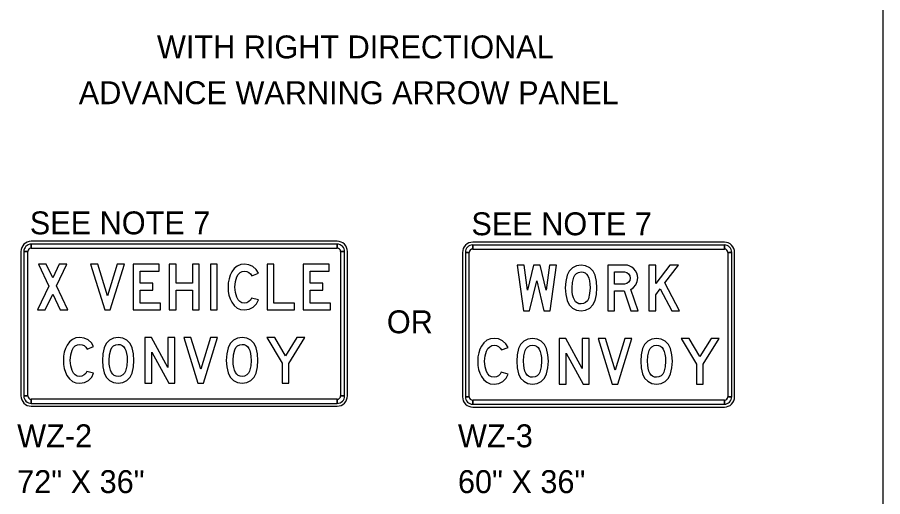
# Model space of a CAD drawing. Extents: x 1416408 to 1429341, y 372694 to 383211.
# Drawn here: x 1427719.8 to 1428099.1, y 373820.1 to 374030.4 of the extents above; entities that cross this region are included whole.
import ezdxf

# ---------------------------------------------------------------- set-up
doc = ezdxf.new("R2010")
doc.units = 0
doc.layers.add('Working Level 1', color=7, linetype='Continuous')

msp = doc.modelspace()

# ---------------------------------------------------------------- linework, layer by layer
at = {"layer": 'Working Level 1'}
for p, q in [((1428099.08, 374447.3), (1428099.08, 372727.17)), ((1427859.99, 373932.16), (1427725.85, 373932.16)), ((1428029.69, 373931.77), (1427919.39, 373931.77)), ((1427721.37, 373927.64), (1427721.37, 373864.35)), ((1427722.62, 373927.64), (1427724.35, 373927.64)), ((1427725.85, 373929.15), (1427725.85, 373930.9)), ((1427859.99, 373930.9), (1427859.99, 373929.15)), ((1427861.48, 373927.64), (1427863.22, 373927.64)), ((1427864.46, 373864.35), (1427864.46, 373927.64)), ((1427919.39, 373928.75), (1427919.39, 373930.51)), ((1428029.69, 373930.51), (1428029.69, 373928.75)), ((1427914.92, 373927.25), (1427914.92, 373863.96)), ((1427916.17, 373927.25), (1427917.9, 373927.25)), ((1428031.18, 373927.25), (1428032.92, 373927.25)), ((1428034.16, 373863.96), (1428034.16, 373927.25)), ((1427724.35, 373864.35), (1427722.62, 373864.35)), ((1427725.85, 373861.08), (1427725.85, 373862.84)), ((1427859.99, 373862.84), (1427859.99, 373861.08)), ((1427863.22, 373864.35), (1427861.48, 373864.35)), ((1427917.9, 373863.96), (1427916.17, 373863.96)), ((1428032.92, 373863.96), (1428031.18, 373863.96)), ((1427725.85, 373859.83), (1427859.99, 373859.83)), ((1427919.39, 373860.69), (1427919.39, 373862.45)), ((1427919.39, 373859.44), (1428029.69, 373859.44)), ((1428029.69, 373862.45), (1428029.69, 373860.69))]:
    msp.add_line(p, q, dxfattribs=at)
for points in [[(1427722.62, 373927.64), (1427722.62, 373864.35), (1427724.35, 373864.35), (1427724.35, 373927.64), (1427722.62, 373927.64)], [(1427859.99, 373930.9), (1427725.85, 373930.9), (1427725.85, 373929.15), (1427859.99, 373929.15), (1427859.99, 373930.9)], [(1427863.22, 373864.35), (1427863.22, 373927.64), (1427861.48, 373927.64), (1427861.48, 373864.35), (1427863.22, 373864.35)], [(1428029.69, 373930.51), (1427919.39, 373930.51), (1427919.39, 373928.75), (1428029.69, 373928.75), (1428029.69, 373930.51)], [(1427916.17, 373927.25), (1427916.17, 373863.96), (1427917.9, 373863.96), (1427917.9, 373927.25), (1427916.17, 373927.25)], [(1428032.92, 373863.96), (1428032.92, 373927.25), (1428031.18, 373927.25), (1428031.18, 373863.96), (1428032.92, 373863.96)], [(1427741.9, 373902.02), (1427736.95, 373912.54), (1427741.49, 373922.11), (1427738.17, 373922.11), (1427735.29, 373916.05), (1427732.43, 373922.11), (1427729.1, 373922.11), (1427733.62, 373912.52), (1427728.64, 373902.02), (1427731.96, 373902.02), (1427735.28, 373909), (1427738.58, 373902.02)], [(1427766.73, 373922.11), (1427763.59, 373922.11), (1427759.32, 373908.23), (1427755.06, 373922.11), (1427751.93, 373922.11), (1427758.08, 373902.02), (1427760.55, 373902.02)], [(1427782.57, 373905.05), (1427773.56, 373905.05), (1427773.56, 373910.74), (1427779.18, 373910.74), (1427779.18, 373913.77), (1427773.56, 373913.77), (1427773.56, 373919.08), (1427781.96, 373919.08), (1427781.96, 373922.11), (1427770.56, 373922.11), (1427770.56, 373902.02), (1427782.57, 373902.02)], [(1427799.52, 373902.02), (1427799.52, 373922.11), (1427796.52, 373922.11), (1427796.52, 373913.77), (1427789.39, 373913.77), (1427789.39, 373922.11), (1427786.39, 373922.11), (1427786.39, 373902.02), (1427789.39, 373902.02), (1427789.39, 373910.74), (1427796.52, 373910.74), (1427796.52, 373902.02)], [(1427807.4, 373902.02), (1427807.4, 373922.11), (1427804.41, 373922.11), (1427804.41, 373902.02)], [(1427825.43, 373906.48), (1427822.43, 373907.25), (1427821.98, 373906.37), (1427821.26, 373905.67), (1427820.32, 373905.21), (1427819.29, 373905.05), (1427818.24, 373905.21), (1427817.35, 373905.69), (1427816.59, 373906.49), (1427815.98, 373907.61), (1427815.37, 373909.67), (1427815.17, 373912.07), (1427815.37, 373914.47), (1427816.01, 373916.54), (1427816.63, 373917.65), (1427817.41, 373918.44), (1427818.32, 373918.92), (1427819.39, 373919.08), (1427820.38, 373918.94), (1427821.28, 373918.52), (1427822.04, 373917.87), (1427822.55, 373917.02), (1427825.43, 373918.17), (1427824.46, 373919.78), (1427823.04, 373921.03), (1427821.32, 373921.84), (1427819.43, 373922.11), (1427817.68, 373921.9), (1427816.16, 373921.27), (1427814.85, 373920.22), (1427813.77, 373918.76), (1427813.07, 373917.31), (1427812.57, 373915.72), (1427812.27, 373913.97), (1427812.17, 373912.08), (1427812.26, 373910.19), (1427812.56, 373908.45), (1427813.05, 373906.85), (1427813.75, 373905.41), (1427814.81, 373903.92), (1427816.1, 373902.87), (1427817.61, 373902.23), (1427819.33, 373902.02), (1427821.35, 373902.33), (1427823.17, 373903.26), (1427824.59, 373904.69)], [(1427841.26, 373902.02), (1427841.26, 373905.05), (1427832.25, 373905.05), (1427832.25, 373922.11), (1427829.25, 373922.11), (1427829.25, 373902.02)], [(1427857.1, 373905.05), (1427848.08, 373905.05), (1427848.08, 373910.74), (1427853.71, 373910.74), (1427853.71, 373913.77), (1427848.08, 373913.77), (1427848.08, 373919.08), (1427856.49, 373919.08), (1427856.49, 373922.11), (1427845.09, 373922.11), (1427845.09, 373902.02), (1427857.1, 373902.02)], [(1427956.1, 373921.72), (1427953.07, 373921.72), (1427951.54, 373910.71), (1427948.91, 373921.72), (1427946.01, 373921.72), (1427943.39, 373910.7), (1427941.87, 373921.72), (1427938.83, 373921.72), (1427941.62, 373901.63), (1427944.32, 373901.63), (1427947.47, 373914.85), (1427950.61, 373901.63), (1427953.32, 373901.63)], [(1427973.82, 373911.69), (1427973.62, 373914.55), (1427973.01, 373917.24), (1427972.12, 373919.05), (1427970.69, 373920.48), (1427968.89, 373921.41), (1427966.87, 373921.72), (1427964.85, 373921.41), (1427963.06, 373920.48), (1427961.65, 373919.04), (1427960.76, 373917.22), (1427960.15, 373914.54), (1427959.95, 373911.69), (1427960.15, 373908.84), (1427960.76, 373906.15), (1427961.65, 373904.32), (1427963.06, 373902.88), (1427964.85, 373901.94), (1427966.87, 373901.63), (1427968.89, 373901.94), (1427970.68, 373902.87), (1427972.1, 373904.29), (1427972.99, 373906.11), (1427973.61, 373908.81)], [(1427991.84, 373901.63), (1427988.7, 373911.01), (1427989.93, 373911.88), (1427990.88, 373913.09), (1427991.5, 373914.52), (1427991.7, 373916.08), (1427991.6, 373917.19), (1427991.29, 373918.23), (1427990.77, 373919.19), (1427990.05, 373920.06), (1427989.18, 373920.79), (1427988.23, 373921.31), (1427987.19, 373921.61), (1427986.08, 373921.72), (1427978.58, 373921.72), (1427978.58, 373901.63), (1427981.58, 373901.63), (1427981.58, 373910.35), (1427985.74, 373910.35), (1427988.68, 373901.63)], [(1428010.05, 373901.63), (1428003.6, 373913.87), (1428009.57, 373921.72), (1428005.79, 373921.72), (1427999.59, 373913.58), (1427999.59, 373921.72), (1427996.59, 373921.72), (1427996.59, 373901.63), (1427999.59, 373901.63), (1427999.59, 373908.61), (1428001.59, 373911.23), (1428006.65, 373901.63)], [(1427970.82, 373911.67), (1427970.64, 373909.23), (1427970.12, 373906.96), (1427969.64, 373906.02), (1427968.89, 373905.28), (1427967.96, 373904.82), (1427966.9, 373904.66), (1427965.96, 373904.77), (1427965.16, 373905.1), (1427964.48, 373905.65), (1427963.93, 373906.42), (1427963.5, 373907.4), (1427963.19, 373908.61), (1427963, 373910.03), (1427962.95, 373911.67), (1427963.12, 373914.1), (1427963.65, 373916.37), (1427964.12, 373917.32), (1427964.87, 373918.06), (1427965.81, 373918.53), (1427966.9, 373918.69), (1427967.81, 373918.58), (1427968.61, 373918.25), (1427969.28, 373917.7), (1427969.84, 373916.93), (1427970.26, 373915.95), (1427970.57, 373914.74), (1427970.76, 373913.31)], [(1427981.58, 373913.38), (1427981.58, 373918.69), (1427985.95, 373918.69), (1427986.9, 373918.49), (1427987.71, 373917.9), (1427988.26, 373917.04), (1427988.44, 373916.03), (1427988.26, 373915.01), (1427987.71, 373914.16), (1427986.9, 373913.57), (1427985.95, 373913.38)], [(1427753.24, 373874.33), (1427750.23, 373875.1), (1427749.79, 373874.22), (1427749.06, 373873.52), (1427748.13, 373873.06), (1427747.09, 373872.91), (1427746.05, 373873.06), (1427745.15, 373873.55), (1427744.4, 373874.35), (1427743.79, 373875.46), (1427743.17, 373877.53), (1427742.97, 373879.92), (1427743.18, 373882.32), (1427743.81, 373884.39), (1427744.44, 373885.5), (1427745.21, 373886.29), (1427746.12, 373886.77), (1427747.19, 373886.93), (1427748.18, 373886.79), (1427749.09, 373886.38), (1427749.84, 373885.72), (1427750.35, 373884.88), (1427753.24, 373886.02), (1427752.26, 373887.63), (1427750.85, 373888.89), (1427749.12, 373889.69), (1427747.24, 373889.96), (1427745.48, 373889.75), (1427743.96, 373889.13), (1427742.66, 373888.08), (1427741.57, 373886.61), (1427740.87, 373885.16), (1427740.37, 373883.57), (1427740.07, 373881.82), (1427739.97, 373879.93), (1427740.07, 373878.04), (1427740.36, 373876.3), (1427740.86, 373874.71), (1427741.55, 373873.26), (1427742.61, 373871.77), (1427743.9, 373870.72), (1427745.41, 373870.08), (1427747.14, 373869.87), (1427749.16, 373870.18), (1427750.97, 373871.11), (1427752.39, 373872.54)], [(1427770.92, 373879.93), (1427770.72, 373882.8), (1427770.12, 373885.48), (1427769.22, 373887.29), (1427767.8, 373888.73), (1427766, 373889.65), (1427763.98, 373889.96), (1427761.95, 373889.65), (1427760.17, 373888.73), (1427758.75, 373887.29), (1427757.86, 373885.46), (1427757.25, 373882.78), (1427757.05, 373879.93), (1427757.25, 373877.08), (1427757.86, 373874.39), (1427758.75, 373872.57), (1427760.17, 373871.13), (1427761.95, 373870.19), (1427763.98, 373869.87), (1427765.99, 373870.18), (1427767.78, 373871.11), (1427769.2, 373872.54), (1427770.1, 373874.36), (1427770.71, 373877.05)], [(1427788.81, 373869.87), (1427788.81, 373889.96), (1427785.81, 373889.96), (1427785.81, 373876.76), (1427778.57, 373889.96), (1427775.68, 373889.96), (1427775.68, 373869.87), (1427778.68, 373869.87), (1427778.68, 373883.5), (1427786.16, 373869.87)], [(1427807.56, 373889.96), (1427804.42, 373889.96), (1427800.15, 373876.08), (1427795.9, 373889.96), (1427792.76, 373889.96), (1427798.92, 373869.87), (1427801.39, 373869.87)], [(1427825.26, 373879.93), (1427825.06, 373882.8), (1427824.46, 373885.48), (1427823.56, 373887.29), (1427822.14, 373888.73), (1427820.34, 373889.65), (1427818.32, 373889.96), (1427816.3, 373889.65), (1427814.51, 373888.73), (1427813.09, 373887.29), (1427812.2, 373885.46), (1427811.59, 373882.78), (1427811.39, 373879.93), (1427811.59, 373877.08), (1427812.2, 373874.39), (1427813.09, 373872.57), (1427814.51, 373871.13), (1427816.3, 373870.19), (1427818.32, 373869.87), (1427820.33, 373870.18), (1427822.13, 373871.11), (1427823.54, 373872.54), (1427824.44, 373874.36), (1427825.05, 373877.05)], [(1427845.75, 373889.96), (1427842.23, 373889.96), (1427837.35, 373881.94), (1427832.58, 373889.96), (1427829.09, 373889.96), (1427835.84, 373878.67), (1427835.84, 373869.87), (1427838.84, 373869.87), (1427838.84, 373878.59)], [(1427934.86, 373873.94), (1427931.86, 373874.71), (1427931.41, 373873.83), (1427930.68, 373873.13), (1427929.75, 373872.67), (1427928.72, 373872.51), (1427927.67, 373872.67), (1427926.78, 373873.15), (1427926.02, 373873.95), (1427925.41, 373875.07), (1427924.8, 373877.13), (1427924.6, 373879.53), (1427924.8, 373881.93), (1427925.43, 373884), (1427926.06, 373885.11), (1427926.84, 373885.9), (1427927.75, 373886.38), (1427928.82, 373886.54), (1427929.81, 373886.4), (1427930.71, 373885.98), (1427931.46, 373885.33), (1427931.98, 373884.49), (1427934.86, 373885.63), (1427933.89, 373887.24), (1427932.47, 373888.5), (1427930.75, 373889.3), (1427928.86, 373889.57), (1427927.11, 373889.36), (1427925.59, 373888.73), (1427924.28, 373887.68), (1427923.2, 373886.22), (1427922.49, 373884.77), (1427922, 373883.18), (1427921.7, 373881.43), (1427921.6, 373879.54), (1427921.69, 373877.65), (1427921.99, 373875.91), (1427922.48, 373874.31), (1427923.18, 373872.87), (1427924.24, 373871.38), (1427925.53, 373870.33), (1427927.04, 373869.69), (1427928.76, 373869.48), (1427930.78, 373869.79), (1427932.6, 373870.72), (1427934.02, 373872.15)], [(1427952.55, 373879.54), (1427952.35, 373882.41), (1427951.74, 373885.09), (1427950.85, 373886.9), (1427949.42, 373888.34), (1427947.62, 373889.26), (1427945.6, 373889.57), (1427943.58, 373889.26), (1427941.79, 373888.34), (1427940.38, 373886.9), (1427939.49, 373885.07), (1427938.88, 373882.39), (1427938.68, 373879.54), (1427938.88, 373876.69), (1427939.49, 373874), (1427940.38, 373872.18), (1427941.79, 373870.74), (1427943.58, 373869.79), (1427945.6, 373869.48), (1427947.62, 373869.79), (1427949.41, 373870.72), (1427950.83, 373872.15), (1427951.72, 373873.97), (1427952.34, 373876.66)], [(1427970.43, 373869.48), (1427970.43, 373889.57), (1427967.43, 373889.57), (1427967.43, 373876.36), (1427960.19, 373889.57), (1427957.31, 373889.57), (1427957.31, 373869.48), (1427960.31, 373869.48), (1427960.31, 373883.11), (1427967.78, 373869.48)], [(1427989.19, 373889.57), (1427986.05, 373889.57), (1427981.78, 373875.69), (1427977.52, 373889.57), (1427974.39, 373889.57), (1427980.54, 373869.48), (1427983.01, 373869.48)], [(1428006.89, 373879.54), (1428006.69, 373882.41), (1428006.08, 373885.09), (1428005.19, 373886.9), (1428003.76, 373888.34), (1428001.96, 373889.26), (1427999.94, 373889.57), (1427997.92, 373889.26), (1427996.13, 373888.34), (1427994.72, 373886.9), (1427993.83, 373885.07), (1427993.22, 373882.39), (1427993.02, 373879.54), (1427993.22, 373876.69), (1427993.83, 373874), (1427994.72, 373872.18), (1427996.13, 373870.74), (1427997.92, 373869.79), (1427999.94, 373869.48), (1428001.96, 373869.79), (1428003.75, 373870.72), (1428005.17, 373872.15), (1428006.07, 373873.97), (1428006.68, 373876.66)], [(1428027.37, 373889.57), (1428023.85, 373889.57), (1428018.98, 373881.55), (1428014.21, 373889.57), (1428010.72, 373889.57), (1428017.47, 373878.28), (1428017.47, 373869.48), (1428020.46, 373869.48), (1428020.46, 373878.2)], [(1427767.92, 373879.92), (1427767.75, 373877.48), (1427767.22, 373875.21), (1427766.74, 373874.26), (1427766, 373873.53), (1427765.06, 373873.06), (1427764, 373872.91), (1427763.07, 373873.01), (1427762.26, 373873.34), (1427761.59, 373873.89), (1427761.03, 373874.66), (1427760.6, 373875.64), (1427760.29, 373876.85), (1427760.11, 373878.27), (1427760.05, 373879.92), (1427760.22, 373882.35), (1427760.75, 373884.61), (1427761.23, 373885.56), (1427761.97, 373886.3), (1427762.91, 373886.77), (1427764, 373886.93), (1427764.91, 373886.82), (1427765.71, 373886.49), (1427766.38, 373885.94), (1427766.94, 373885.18), (1427767.37, 373884.19), (1427767.68, 373882.99), (1427767.86, 373881.56)], [(1427822.27, 373879.92), (1427822.09, 373877.48), (1427821.56, 373875.21), (1427821.08, 373874.26), (1427820.34, 373873.53), (1427819.4, 373873.06), (1427818.34, 373872.91), (1427817.41, 373873.01), (1427816.61, 373873.34), (1427815.93, 373873.89), (1427815.38, 373874.66), (1427814.94, 373875.64), (1427814.64, 373876.85), (1427814.45, 373878.27), (1427814.39, 373879.92), (1427814.57, 373882.35), (1427815.1, 373884.61), (1427815.57, 373885.56), (1427816.31, 373886.3), (1427817.26, 373886.77), (1427818.34, 373886.93), (1427819.26, 373886.82), (1427820.05, 373886.49), (1427820.73, 373885.94), (1427821.28, 373885.18), (1427821.71, 373884.19), (1427822.02, 373882.99), (1427822.2, 373881.56)], [(1427949.55, 373879.53), (1427949.37, 373877.09), (1427948.85, 373874.82), (1427948.37, 373873.87), (1427947.62, 373873.14), (1427946.69, 373872.67), (1427945.63, 373872.51), (1427944.69, 373872.62), (1427943.89, 373872.95), (1427943.21, 373873.5), (1427942.66, 373874.27), (1427942.23, 373875.25), (1427941.92, 373876.46), (1427941.73, 373877.88), (1427941.68, 373879.53), (1427941.85, 373881.96), (1427942.38, 373884.22), (1427942.85, 373885.17), (1427943.6, 373885.91), (1427944.54, 373886.38), (1427945.63, 373886.54), (1427946.54, 373886.43), (1427947.34, 373886.1), (1427948.01, 373885.55), (1427948.57, 373884.79), (1427948.99, 373883.8), (1427949.3, 373882.6), (1427949.49, 373881.17)], [(1428003.89, 373879.53), (1428003.71, 373877.09), (1428003.19, 373874.82), (1428002.71, 373873.87), (1428001.96, 373873.14), (1428001.03, 373872.67), (1427999.97, 373872.51), (1427999.03, 373872.62), (1427998.23, 373872.95), (1427997.55, 373873.5), (1427997, 373874.27), (1427996.57, 373875.25), (1427996.26, 373876.46), (1427996.08, 373877.88), (1427996.02, 373879.53), (1427996.19, 373881.96), (1427996.72, 373884.22), (1427997.19, 373885.17), (1427997.94, 373885.91), (1427998.88, 373886.38), (1427999.97, 373886.54), (1428000.88, 373886.43), (1428001.68, 373886.1), (1428002.35, 373885.55), (1428002.91, 373884.79), (1428003.33, 373883.8), (1428003.64, 373882.6), (1428003.83, 373881.17)], [(1427725.85, 373861.08), (1427859.99, 373861.08), (1427859.99, 373862.84), (1427725.85, 373862.84), (1427725.85, 373861.08)], [(1427919.39, 373860.69), (1428029.69, 373860.69), (1428029.69, 373862.45), (1427919.39, 373862.45), (1427919.39, 373860.69)]]:
    msp.add_lwpolyline(points, close=True, dxfattribs=at)
for centre, major_axis, start_param, end_param in [((1427725.85, 373927.64), (0, 4.52), 0.000004, 1.570794), ((1427859.99, 373927.64), (0, 4.52), 4.712389, 6.283189), ((1427919.39, 373927.25), (0, 4.52), 0.000004, 1.570794), ((1428029.69, 373927.25), (0, 4.52), 4.712389, 6.283189), ((1427725.85, 373927.64), (0, 3.27), 0.000004, 1.570794), ((1427725.85, 373927.64), (0, 1.51), 0.000004, 1.570794), ((1427859.99, 373927.64), (0, 3.27), 4.712389, 6.283189), ((1427859.99, 373927.64), (0, 1.51), 4.712389, 6.283189), ((1427919.39, 373927.25), (0, 3.27), 0.000004, 1.570794), ((1427919.39, 373927.25), (0, 1.51), 0.000004, 1.570794), ((1428029.69, 373927.25), (0, 3.27), 4.712389, 6.283189), ((1428029.69, 373927.25), (0, 1.51), 4.712389, 6.283189), ((1427725.85, 373864.35), (0, 4.52), 1.570794, 3.141594), ((1427725.85, 373864.35), (0, 3.27), 1.570794, 3.141594), ((1427725.85, 373864.35), (0, 1.51), 1.570794, 3.141594), ((1427859.99, 373864.35), (0, 4.52), 3.141594, 4.712394), ((1427859.99, 373864.35), (0, 3.27), 3.141594, 4.712394), ((1427859.99, 373864.35), (0, 1.51), 3.141594, 4.712394), ((1427919.39, 373863.96), (0, 4.52), 1.570794, 3.141594), ((1427919.39, 373863.96), (0, 3.27), 1.570794, 3.141594), ((1427919.39, 373863.96), (0, 1.51), 1.570794, 3.141594), ((1428029.69, 373863.96), (0, 4.52), 3.141594, 4.712394), ((1428029.69, 373863.96), (0, 3.27), 3.141594, 4.712394), ((1428029.69, 373863.96), (0, 1.51), 3.141594, 4.712394)]:
    msp.add_ellipse(centre, major_axis=major_axis, ratio=0.989089, start_param=start_param, end_param=end_param, dxfattribs=at)

# ---------------------------------------------------------------- texts
for s, p in [('WITH RIGHT DIRECTIONAL', (1427780.99, 374012.37)), ('ADVANCE WARNING ARROW PANEL', (1427746.72, 373992.28)), ('SEE NOTE 7 ', (1427725.25, 373935.19)), ('SEE NOTE 7 ', (1427918.8, 373934.79))]:
    msp.add_text(s, height=10.0465, dxfattribs=at).set_placement(p)
for s, p in [('OR', (1427881.75, 373891.81)), ('WZ-2', (1427719.72, 373841.81)), ('WZ-3', (1427912.91, 373841.81)), ('72" X 36"', (1427719.72, 373821.72)), ('60" X 36"', (1427912.91, 373821.72))]:
    msp.add_text(s, height=10.046, rotation=0, dxfattribs=at).set_placement(p)

doc.saveas('drawing.dxf')
